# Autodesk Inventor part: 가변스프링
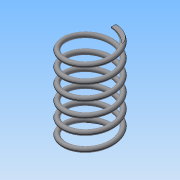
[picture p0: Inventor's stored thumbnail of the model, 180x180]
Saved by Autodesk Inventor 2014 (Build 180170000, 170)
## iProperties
Created: 2020-08
Part Number: 가변스프링
Material: 일반
Document SubType Name: Modeling
Designer: net
Density: 1 g/cm^3
Appearance: 기본값
Mass: 9.37176 g
Surface Area: 94.777 cm^2
Volume: 9.37176 cm^3
Author: net
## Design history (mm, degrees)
sketch "스케치1"
  geometry: L1 (0, 0)-(20, 0); L2 (20, 0)-(20, 75.25); L3 (20, 75.25)-(0, 75.25); L4 (0, 75.25)-(0, 0); C1 r 2 at (20, 0)
  constraints: 8 end point, 2 parallel, 1 centre point, 1 coincident, 1 horizontal, 1 perpendicular
  dimensions: "d0" = 4 diameter of C1; "d1" = 40 diameter of L2 L4; "d2" = 75.25 distance between parallel lines of L1 L3 (derived)
feature "코일1" sketch "스케치1" pitch "d3" = 10; turns "d5" = 6; dims "d4" = 75.25 (= d2), "d6" = 0, angle "d7" = 90 deg, angle "d8" = 90 deg, "d9" = 0, "d10" = 0
node "작업 평면1"
sketch "스케치2"
  geometry: L1 (0, 18)-(0, 22) reference; 1 further point
  constraints: 1 vertical alignment
extrude "돌출1" cut sketch "스케치2" distance "d11" = 10; taper "d12" = 0 deg
node "작업 평면2"
sketch "스케치3"
  geometry: L1 (0, 18)-(0, 22) reference; 1 further point
  constraints: 1 vertical alignment
extrude "돌출2" cut sketch "스케치3" distance "d13" = 10; taper "d14" = 0 deg
node "솔리드1"
node "절단 모서리 투영1"
node "절단 모서리 투영2"
